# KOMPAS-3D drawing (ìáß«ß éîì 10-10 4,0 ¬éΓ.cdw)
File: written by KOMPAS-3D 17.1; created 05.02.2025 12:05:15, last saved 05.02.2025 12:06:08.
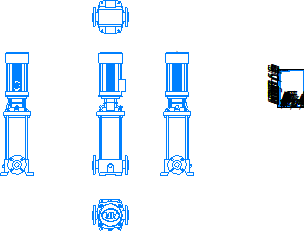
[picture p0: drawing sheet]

Sheet 1: A4, portrait

Title block, sheet 1: name: Насос ВМН 10-10 / 4,0 кВт; designation: Насос ВМН 10-10 4,0 кВт; material: Сталь 10  ГОСТ 1050-2013; mass: 175,75; sheets: 1; sheet format: A4; stored path: \\adlc.lan\data\АДЛ_ПКД\3D-модели\ADL production\Насосы ГРАНПАМП\Насосы ВМН\ВМН10\KOMPAS 3D\Насос ВМН 10-10 4,0 кВт.cdw

Views: Вид 1, Спереди, Проекционный вид 2, Проекционный вид 3, Проекционный вид 4, Проекционный вид 5
Referenced files in \\adlc.lan\data\АДЛ_ПКД\3D-модели\ADL production\Насосы ГРАНПАМП\Насосы ВМН\ВМН10\KOMPAS 3D\: Насос ВМН 10-10 4,0 кВт.m3d
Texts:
  Andrey
  АДЛ
Dimensions and other numbers on the sheet: 1:1; 1; 4,0 кВт; 175,75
